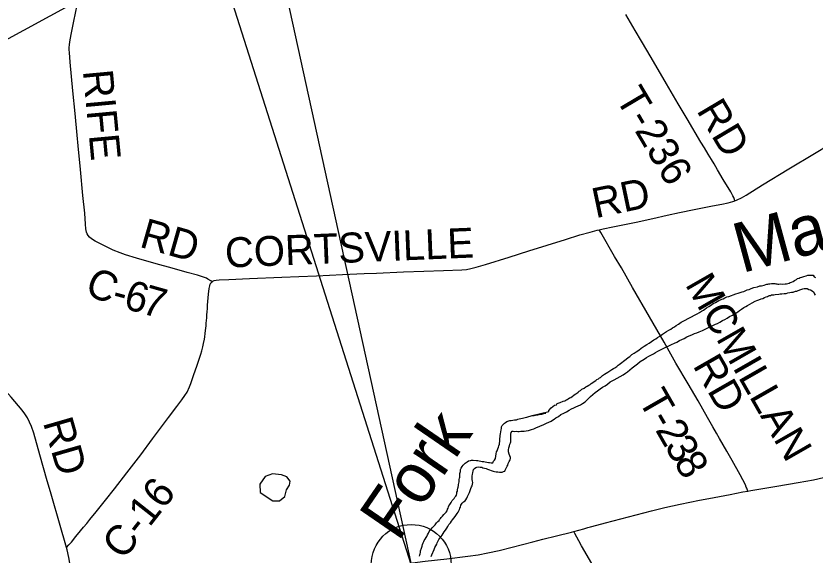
# Model space of a CAD drawing. Extents: x -19.5 to 44.1, y 0 to 22.
# Drawn here: x -17.011 to -15.494, y 5.391 to 6.414 of the extents above; entities that cross this region are included whole.
import ezdxf

# ---------------------------------------------------------------- set-up
doc = ezdxf.new("R2010")
doc.units = 0
for name, color, linetype in [('GM_X_County_Road', 7, 'Continuous'), ('GM_X_County_Road_Text', 7, 'Continuous'), ('GM_X_Minor_Lake', 7, 'Continuous'), ('GM_X_Minor_River', 7, 'Continuous'), ('GM_X_Minor_River_Text', 7, 'Continuous'), ('GM_X_Township', 7, 'Continuous'), ('GM_X_Township_Road', 7, 'Continuous'), ('GM_X_Township_Road_Text', 7, 'Continuous'), ('GM_X_US_Route', 7, 'Continuous'), ('SH_Text', 7, 'Continuous')]:
    doc.layers.add(name, color=color, linetype=linetype)

msp = doc.modelspace()

# ---------------------------------------------------------------- linework, layer by layer
at = {"layer": 'GM_X_County_Road'}
for points in [[(-16.6388, 5.9099), (-16.6413, 5.9114), (-16.6469, 5.9148), (-16.6497, 5.9164), (-16.6533, 5.918), (-16.6668, 5.9221), (-16.6859, 5.9276), (-16.7147, 5.9355), (-16.7452, 5.9441), (-16.7822, 5.9547), (-16.803, 5.9608), (-16.8135, 5.9645), (-16.8267, 5.97), (-16.8407, 5.9766), (-16.8606, 5.9868), (-16.868, 5.9911), (-16.8716, 5.9942), (-16.8741, 5.9975), (-16.8758, 6.0006), (-16.877, 6.004), (-16.8782, 6.01), (-16.8789, 6.0192), (-16.8806, 6.0397), (-16.884, 6.0737), (-16.8887, 6.1231), (-16.893, 6.1677), (-16.895, 6.188), (-16.8985, 6.2289), (-16.9031, 6.2721), (-16.9084, 6.3265), (-16.9095, 6.3451), (-16.9099, 6.3499), (-16.9099, 6.3542), (-16.9096, 6.3592), (-16.9088, 6.3653), (-16.9063, 6.3794), (-16.9011, 6.4043), (-16.8948, 6.4348)], [(-15.6467, 6.0636), (-15.642, 6.0653), (-15.6342, 6.069), (-15.6251, 6.0743), (-15.5939, 6.0935), (-15.544, 6.1239), (-15.4957, 6.1532), (-15.468, 6.1698)], [(-15.904, 6.0085), (-15.8967, 6.0102), (-15.8784, 6.014), (-15.834, 6.0232), (-15.8024, 6.03), (-15.7751, 6.0359), (-15.7515, 6.041), (-15.7235, 6.0468), (-15.6888, 6.0538), (-15.6711, 6.0573), (-15.659, 6.0597), (-15.6507, 6.0621), (-15.6467, 6.0636)], [(-16.6388, 5.9099), (-16.6375, 5.9108), (-16.6351, 5.912), (-16.6314, 5.9129), (-16.6257, 5.9135), (-16.607, 5.9144), (-16.5679, 5.9159), (-16.5064, 5.9186), (-16.4742, 5.9199), (-16.4407, 5.9213), (-16.3916, 5.9234), (-16.3501, 5.9253), (-16.3265, 5.9261), (-16.2756, 5.9285), (-16.2371, 5.9297), (-16.1993, 5.9313), (-16.1645, 5.9326), (-16.1559, 5.9333), (-16.1474, 5.9348), (-16.1379, 5.9372), (-16.12, 5.9425), (-16.075, 5.9567), (-16.0376, 5.9682), (-15.9683, 5.9902), (-15.9411, 5.9987), (-15.9214, 6.0042), (-15.9081, 6.0075), (-15.904, 6.0085)], [(-16.9154, 5.4056), (-16.9176, 5.4142), (-16.926, 5.4428), (-16.9456, 5.5108), (-16.9516, 5.5317), (-16.9658, 5.5813), (-16.9773, 5.6226), (-16.9815, 5.6349), (-16.9851, 5.6434), (-16.9894, 5.6516), (-16.9943, 5.6594), (-16.9991, 5.6659), (-17.0061, 5.6745), (-17.0204, 5.6908), (-17.0513, 5.7249), (-17.0867, 5.764), (-17.1123, 5.792), (-17.1327, 5.8146), (-17.1747, 5.862), (-17.2117, 5.9039), (-17.2222, 5.9152), (-17.2291, 5.9215), (-17.234, 5.9253)], [(-16.9154, 5.4056), (-16.9109, 5.4102), (-16.9083, 5.4129), (-16.9058, 5.4158), (-16.8973, 5.4262), (-16.8883, 5.4372), (-16.8828, 5.4439), (-16.8769, 5.4511), (-16.8711, 5.4583), (-16.859, 5.4731), (-16.8489, 5.4857), (-16.8412, 5.4954), (-16.8243, 5.5168), (-16.8005, 5.5471), (-16.7741, 5.5816), (-16.7519, 5.6116), (-16.7422, 5.6245), (-16.7214, 5.6524), (-16.7058, 5.6732), (-16.6964, 5.6856), (-16.6904, 5.6942), (-16.6864, 5.7004), (-16.6816, 5.7104), (-16.6791, 5.7167), (-16.6771, 5.7225), (-16.6739, 5.7319), (-16.6674, 5.7514), (-16.6602, 5.7725), (-16.6583, 5.779), (-16.6564, 5.7862), (-16.655, 5.7928), (-16.6534, 5.8007), (-16.6527, 5.8055), (-16.6518, 5.8116), (-16.6512, 5.8171), (-16.6503, 5.8263), (-16.6498, 5.8313), (-16.6491, 5.8411), (-16.6486, 5.8473), (-16.6483, 5.8528), (-16.6478, 5.859), (-16.6475, 5.8652), (-16.6456, 5.8862), (-16.6444, 5.8967), (-16.6433, 5.9023), (-16.6423, 5.9054), (-16.641, 5.9077), (-16.6396, 5.9092), (-16.6388, 5.9099)], [(-16.8811, 5.1933), (-16.8824, 5.1992), (-16.8847, 5.2096), (-16.8873, 5.2262), (-16.8926, 5.2612), (-16.8985, 5.3055), (-16.9024, 5.332), (-16.9066, 5.3602), (-16.911, 5.3865), (-16.9142, 5.401), (-16.9154, 5.4056)]]:
    msp.add_lwpolyline(points, dxfattribs=at)
at = {"layer": 'GM_X_Minor_Lake'}
for points in [[(-16.5244, 5.545), (-16.5382, 5.5404), (-16.5479, 5.5257), (-16.5478, 5.5098), (-16.5238, 5.4937), (-16.5109, 5.4939), (-16.5009, 5.502), (-16.4976, 5.5149), (-16.4918, 5.5235), (-16.4909, 5.5311), (-16.4968, 5.5395)], [(-16.4968, 5.5395), (-16.5069, 5.5432), (-16.5244, 5.545)]]:
    msp.add_lwpolyline(points, dxfattribs=at)
at = {"layer": 'GM_X_Minor_River'}
for points in [[(-15.6367, 5.8894), (-15.6329, 5.8905), (-15.6294, 5.8916), (-15.6268, 5.8927), (-15.6233, 5.8942), (-15.6195, 5.8953), (-15.6157, 5.8967), (-15.6104, 5.8986), (-15.6035, 5.9004), (-15.5993, 5.9018), (-15.5963, 5.9022), (-15.5932, 5.9029), (-15.5909, 5.9036), (-15.5879, 5.9043), (-15.5856, 5.905), (-15.5837, 5.9054), (-15.5818, 5.9058), (-15.5799, 5.9061), (-15.5772, 5.9064), (-15.5731, 5.9064), (-15.5708, 5.9064), (-15.5689, 5.9059), (-15.567, 5.9059), (-15.5651, 5.9055), (-15.5628, 5.9055), (-15.559, 5.9058), (-15.5552, 5.9054), (-15.551, 5.9061), (-15.5484, 5.906), (-15.5457, 5.9068), (-15.5434, 5.9071), (-15.5415, 5.9082), (-15.5388, 5.9093), (-15.5362, 5.9104), (-15.5331, 5.9123), (-15.5297, 5.9141), (-15.5278, 5.916), (-15.5243, 5.9167), (-15.5224, 5.9178), (-15.5197, 5.9185), (-15.5159, 5.92), (-15.5114, 5.9211), (-15.5083, 5.9226), (-15.5045, 5.9225), (-15.5007, 5.9224), (-15.4981, 5.9224), (-15.4958, 5.919), (-15.4936, 5.9178)], [(-16.031, 5.6557), (-15.9998, 5.6633), (-15.9994, 5.6655), (-15.9951, 5.6708), (-15.989, 5.6756), (-15.9852, 5.6763), (-15.9836, 5.6786), (-15.9783, 5.6808), (-15.9726, 5.683), (-15.9695, 5.6837), (-15.9672, 5.6848), (-15.9649, 5.6863), (-15.9627, 5.6874), (-15.9607, 5.6893), (-15.9577, 5.6904), (-15.9554, 5.6919), (-15.9519, 5.6945), (-15.9496, 5.6964), (-15.9473, 5.6978), (-15.9439, 5.7005), (-15.942, 5.7019), (-15.9397, 5.7034), (-15.937, 5.7057), (-15.9328, 5.7079), (-15.9297, 5.7101), (-15.927, 5.7116), (-15.924, 5.7135), (-15.9213, 5.7149), (-15.919, 5.7164), (-15.9163, 5.7187), (-15.9133, 5.7205), (-15.9106, 5.7224), (-15.9083, 5.7243), (-15.9056, 5.7257), (-15.9037, 5.7272), (-15.9018, 5.7283), (-15.8976, 5.7321), (-15.8941, 5.7343), (-15.8911, 5.7362), (-15.8876, 5.7384), (-15.8838, 5.741), (-15.88, 5.7432), (-15.8769, 5.7451), (-15.8742, 5.7466), (-15.8708, 5.7488), (-15.8681, 5.7514), (-15.8662, 5.7525), (-15.8639, 5.7544), (-15.8554, 5.7611), (-15.8527, 5.763), (-15.8493, 5.766), (-15.8459, 5.7682), (-15.8424, 5.7719), (-15.8374, 5.7742), (-15.8336, 5.7771), (-15.829, 5.7801), (-15.8244, 5.7838), (-15.819, 5.7876), (-15.8137, 5.7905), (-15.8095, 5.7935), (-15.8049, 5.7965), (-15.8003, 5.7995), (-15.7968, 5.8017), (-15.7934, 5.8043), (-15.7892, 5.8065), (-15.7865, 5.8084), (-15.7838, 5.8102), (-15.78, 5.8128), (-15.7762, 5.8155), (-15.772, 5.8177), (-15.7681, 5.8199), (-15.7647, 5.8225), (-15.7612, 5.8244), (-15.7582, 5.8266), (-15.7536, 5.8296), (-15.7486, 5.8333), (-15.7406, 5.837), (-15.7349, 5.8399), (-15.7287, 5.8433), (-15.723, 5.8462), (-15.718, 5.8488), (-15.7135, 5.8514), (-15.7096, 5.854), (-15.7062, 5.8559), (-15.7035, 5.8577), (-15.7001, 5.8603), (-15.6962, 5.8626), (-15.6912, 5.8659), (-15.6878, 5.8685), (-15.6836, 5.8707), (-15.6802, 5.8726), (-15.6771, 5.8741), (-15.674, 5.8755), (-15.6714, 5.8766), (-15.6687, 5.8777), (-15.6653, 5.8792), (-15.6618, 5.8811), (-15.658, 5.8821), (-15.6447, 5.8869), (-15.6405, 5.8884), (-15.6367, 5.8894)], [(-15.9813, 5.6543), (-15.9767, 5.6576), (-15.9713, 5.6606), (-15.9664, 5.6632), (-15.961, 5.6661), (-15.9564, 5.6683), (-15.9522, 5.6702), (-15.9484, 5.6724), (-15.9438, 5.6746), (-15.9396, 5.6765), (-15.9358, 5.6787), (-15.9308, 5.682), (-15.9278, 5.685), (-15.9243, 5.6884), (-15.9205, 5.6918), (-15.9162, 5.6959), (-15.9116, 5.6996), (-15.907, 5.703), (-15.9021, 5.7063), (-15.8975, 5.7097), (-15.8929, 5.7123), (-15.8883, 5.7156), (-15.8833, 5.7201), (-15.8756, 5.7234), (-15.8699, 5.7267), (-15.8642, 5.7301), (-15.8588, 5.7334), (-15.8542, 5.736), (-15.8504, 5.739), (-15.8458, 5.7427), (-15.8412, 5.7465), (-15.8366, 5.7502), (-15.8316, 5.7543), (-15.8262, 5.7584), (-15.819, 5.7629), (-15.8144, 5.7658), (-15.8098, 5.7684), (-15.8048, 5.771), (-15.801, 5.7729), (-15.7975, 5.7755), (-15.793, 5.7781), (-15.788, 5.7807), (-15.7826, 5.7832), (-15.767, 5.791), (-15.7609, 5.7932), (-15.7567, 5.7954), (-15.7517, 5.798), (-15.7471, 5.8002), (-15.7425, 5.8024), (-15.7379, 5.805), (-15.733, 5.8069), (-15.7284, 5.8091), (-15.7234, 5.8117), (-15.7185, 5.8131), (-15.7143, 5.8149), (-15.7078, 5.8175), (-15.7028, 5.8201), (-15.6979, 5.8223), (-15.6933, 5.8241), (-15.6883, 5.8267), (-15.6834, 5.8293), (-15.6792, 5.8308), (-15.675, 5.8334), (-15.67, 5.836), (-15.6654, 5.8382), (-15.6612, 5.8408), (-15.657, 5.8438), (-15.6512, 5.8463), (-15.6478, 5.8482), (-15.6444, 5.8504), (-15.6409, 5.853), (-15.6375, 5.8553), (-15.634, 5.8579), (-15.6298, 5.8608), (-15.626, 5.8631), (-15.6225, 5.8649), (-15.6183, 5.8675), (-15.6137, 5.8701), (-15.608, 5.8727), (-15.6046, 5.8742), (-15.6008, 5.8756), (-15.5966, 5.8775), (-15.5935, 5.8782), (-15.5905, 5.8797), (-15.5874, 5.8811), (-15.5847, 5.8819), (-15.5828, 5.883), (-15.5805, 5.8837), (-15.5786, 5.884), (-15.5767, 5.8848), (-15.5745, 5.8847), (-15.5726, 5.8851), (-15.5699, 5.8858), (-15.5634, 5.8865), (-15.5604, 5.8868), (-15.5573, 5.8872), (-15.5532, 5.8875), (-15.5494, 5.8878), (-15.5463, 5.8889), (-15.5421, 5.8892), (-15.5391, 5.8899)], [(-15.5391, 5.8899), (-15.536, 5.8903), (-15.5315, 5.8917), (-15.5292, 5.8921), (-15.5265, 5.8932), (-15.5212, 5.895), (-15.5174, 5.8961), (-15.5147, 5.8968), (-15.512, 5.8971), (-15.5094, 5.8967), (-15.506, 5.8952), (-15.503, 5.8944), (-15.4999, 5.8928), (-15.4969, 5.8901), (-15.4962, 5.8878), (-15.4944, 5.8844)], [(-16.031, 5.6557), (-16.0276, 5.6561), (-16.0249, 5.6568), (-16.0226, 5.6575), (-16.0207, 5.6575), (-16.0147, 5.6582), (-16.0128, 5.6585), (-16.0108, 5.6589), (-16.0089, 5.6596), (-16.0063, 5.6603), (-16.0055, 5.6606)], [(-16.1962, 5.4708), (-16.1947, 5.4727), (-16.1927, 5.4749), (-16.1919, 5.4783), (-16.1908, 5.4802), (-16.19, 5.4825), (-16.1892, 5.4844), (-16.1873, 5.487), (-16.1853, 5.4908), (-16.183, 5.4945), (-16.1811, 5.4968), (-16.1795, 5.4987), (-16.178, 5.5009), (-16.1764, 5.5028), (-16.1749, 5.5047), (-16.1745, 5.5081), (-16.1741, 5.5104), (-16.1733, 5.5122), (-16.1729, 5.5149), (-16.1724, 5.5179), (-16.172, 5.5202), (-16.1712, 5.5232), (-16.1712, 5.5251), (-16.1708, 5.5278), (-16.17, 5.5301), (-16.1696, 5.5323), (-16.1696, 5.5346), (-16.1692, 5.5369), (-16.1688, 5.5388), (-16.1687, 5.5411), (-16.1683, 5.543), (-16.1683, 5.5456), (-16.1679, 5.5475), (-16.1675, 5.5494), (-16.1671, 5.5532), (-16.1659, 5.5562), (-16.1643, 5.5589), (-16.162, 5.5619), (-16.1586, 5.5652), (-16.1544, 5.5682), (-16.1521, 5.5697), (-16.1486, 5.5708), (-16.1467, 5.5711), (-16.1433, 5.5715), (-16.1372, 5.5706), (-16.1342, 5.5706), (-16.1316, 5.5698), (-16.1289, 5.5694), (-16.1259, 5.5689), (-16.1232, 5.5685), (-16.1206, 5.5681), (-16.1172, 5.5677), (-16.1141, 5.5669), (-16.1122, 5.5668), (-16.1092, 5.5664), (-16.1062, 5.5664), (-16.1046, 5.5694), (-16.1031, 5.5713), (-16.1011, 5.5743), (-16.1003, 5.5788), (-16.0995, 5.5834), (-16.0987, 5.5872), (-16.0979, 5.5891), (-16.0963, 5.5925), (-16.0952, 5.5959), (-16.0944, 5.5981), (-16.0936, 5.6015), (-16.0932, 5.6034), (-16.0927, 5.6065), (-16.0927, 5.6091), (-16.0927, 5.6122), (-16.0923, 5.6156), (-16.0918, 5.6182), (-16.0914, 5.6213), (-16.0902, 5.6288), (-16.0898, 5.6315), (-16.0894, 5.6342), (-16.0882, 5.6368), (-16.0859, 5.6398), (-16.084, 5.6413), (-16.0817, 5.6424), (-16.0794, 5.6443), (-16.0759, 5.6457), (-16.074, 5.6465), (-16.071, 5.6464), (-16.0679, 5.6468), (-16.0649, 5.6475), (-16.063, 5.6475), (-16.0611, 5.6478), (-16.0584, 5.6489), (-16.0558, 5.6496), (-16.0531, 5.65), (-16.0497, 5.6511), (-16.047, 5.6518), (-16.0443, 5.6521), (-16.0417, 5.6525), (-16.0394, 5.6532), (-16.0375, 5.6539), (-16.0352, 5.6546), (-16.0333, 5.6554), (-16.031, 5.6557)], [(-16.1866, 5.4524), (-16.1842, 5.4554), (-16.1827, 5.458), (-16.18, 5.4614), (-16.1777, 5.4641), (-16.175, 5.4678), (-16.1734, 5.4701), (-16.1719, 5.4723), (-16.1703, 5.4753), (-16.1692, 5.4776), (-16.1684, 5.4803), (-16.1676, 5.4821), (-16.1668, 5.4856), (-16.1641, 5.4893), (-16.1614, 5.4919), (-16.1587, 5.4938), (-16.1572, 5.4961), (-16.1552, 5.4991), (-16.154, 5.5025), (-16.1521, 5.5062), (-16.1505, 5.51), (-16.149, 5.5134), (-16.1474, 5.5172), (-16.1462, 5.5206), (-16.1451, 5.5225), (-16.1438, 5.5289), (-16.1446, 5.5316), (-16.1449, 5.5346), (-16.1452, 5.5381), (-16.1452, 5.5415), (-16.1448, 5.5441), (-16.144, 5.5479), (-16.1432, 5.5506), (-16.1424, 5.5532), (-16.1405, 5.5551), (-16.1385, 5.557), (-16.1363, 5.5581), (-16.134, 5.5584), (-16.1298, 5.558), (-16.1271, 5.5579), (-16.1249, 5.5568), (-16.1219, 5.5563), (-16.1184, 5.5552), (-16.1162, 5.5544), (-16.1143, 5.5536), (-16.1124, 5.5528), (-16.109, 5.5516), (-16.1052, 5.5504), (-16.1026, 5.5496), (-16.0999, 5.5488), (-16.0965, 5.5488), (-16.0935, 5.5487), (-16.0904, 5.5487), (-16.0885, 5.5486), (-16.0855, 5.5497), (-16.0832, 5.5505), (-16.0824, 5.5524), (-16.0785, 5.5595), (-16.0777, 5.5618), (-16.0766, 5.5648), (-16.075, 5.5686), (-16.0731, 5.5716), (-16.0723, 5.5742), (-16.0722, 5.5761), (-16.0737, 5.5792), (-16.0748, 5.5823), (-16.0763, 5.5868), (-16.0762, 5.5906), (-16.0758, 5.5944), (-16.0746, 5.5986), (-16.0734, 5.6016), (-16.0723, 5.6039), (-16.0719, 5.6058), (-16.0718, 5.6096), (-16.0718, 5.6122), (-16.0718, 5.6141), (-16.0721, 5.6164), (-16.0717, 5.6206), (-16.0713, 5.6236), (-16.069, 5.6263), (-16.0671, 5.6262), (-16.0648, 5.6258), (-16.0618, 5.6262), (-16.0587, 5.6257), (-16.0557, 5.6257), (-16.0526, 5.626), (-16.0496, 5.6264), (-16.0466, 5.6263), (-16.0428, 5.627), (-16.0382, 5.6277), (-16.0325, 5.6295), (-16.0283, 5.6306), (-16.0241, 5.6325), (-16.0092, 5.6391), (-16.0042, 5.6413), (-15.9997, 5.6435), (-15.9955, 5.6453), (-15.9924, 5.6472), (-15.9893, 5.649), (-15.9863, 5.6517), (-15.9813, 5.6543)], [(-16.2454, 5.3887), (-16.2446, 5.3913), (-16.2439, 5.3936), (-16.2434, 5.3958), (-16.243, 5.3993), (-16.2414, 5.4042), (-16.2403, 5.408), (-16.2395, 5.411), (-16.2379, 5.414), (-16.2367, 5.4166), (-16.236, 5.4185), (-16.2344, 5.4212), (-16.2328, 5.4242), (-16.2313, 5.4264), (-16.2297, 5.4295), (-16.2282, 5.4325), (-16.2266, 5.4359), (-16.2247, 5.4381), (-16.2231, 5.4404), (-16.2212, 5.443), (-16.2151, 5.4483), (-16.2131, 5.4524), (-16.2101, 5.4546), (-16.2081, 5.4569), (-16.207, 5.4588), (-16.2054, 5.4607), (-16.2039, 5.4625), (-16.2016, 5.4652), (-16.1989, 5.4678), (-16.1962, 5.4708)], [(-16.2227, 5.3883), (-16.2215, 5.3917), (-16.2176, 5.4019), (-16.216, 5.4057), (-16.2141, 5.4087), (-16.2125, 5.4117), (-16.2113, 5.414), (-16.2102, 5.417), (-16.2082, 5.4204), (-16.2063, 5.4234), (-16.2043, 5.4261), (-16.2024, 5.4291), (-16.2001, 5.4321), (-16.1982, 5.4351), (-16.1958, 5.4381), (-16.1931, 5.4422), (-16.1912, 5.4456), (-16.1893, 5.449), (-16.1866, 5.4524)]]:
    msp.add_lwpolyline(points, dxfattribs=at)
at = {"layer": 'GM_X_Township'}
msp.add_lwpolyline([(-12.8914, 6.3794), (-13.1137, 6.4041), (-13.3583, 6.4294), (-13.4411, 6.4345), (-13.5998, 6.4444), (-14.0891, 6.4899), (-14.1777, 7.0231), (-14.285, 7.035), (-14.659, 7.083), (-15.5678, 7.2141), (-15.56, 7.1963), (-16.1193, 6.8606), (-16.1939, 6.8159), (-16.2133, 6.8121), (-16.897, 6.4411), (-17.1473, 6.3052)], dxfattribs=at)
at = {"layer": 'GM_X_Township_Road'}
for points in [[(-15.6467, 6.0636), (-15.6475, 6.0658), (-15.6487, 6.0695), (-15.6503, 6.0728), (-15.6545, 6.0806), (-15.6685, 6.104), (-15.6796, 6.122), (-15.686, 6.1334), (-15.691, 6.1419), (-15.6971, 6.1518), (-15.7044, 6.164), (-15.7112, 6.1749), (-15.7371, 6.2188), (-15.7541, 6.2477), (-15.7761, 6.2852), (-15.8056, 6.3356), (-15.8239, 6.3666), (-15.8359, 6.387), (-15.8537, 6.4168)], [(-15.6221, 5.5126), (-15.624, 5.5179), (-15.6248, 5.5202), (-15.6265, 5.5242), (-15.6367, 5.5434), (-15.6517, 5.5706), (-15.6617, 5.5884), (-15.6756, 5.6126), (-15.6813, 5.6223), (-15.6882, 5.6347), (-15.6985, 5.6524), (-15.7164, 5.6837), (-15.7352, 5.7159), (-15.7583, 5.7556), (-15.7809, 5.7949), (-15.8088, 5.8433), (-15.8406, 5.8988), (-15.8619, 5.936), (-15.8748, 5.9579), (-15.9009, 6.003), (-15.904, 6.0085)], [(-15.7034, 5.0119), (-15.7159, 5.033), (-15.7253, 5.049), (-15.7408, 5.0753), (-15.7528, 5.0956), (-15.7647, 5.116), (-15.7726, 5.1293), (-15.784, 5.1485), (-15.8027, 5.1794), (-15.8226, 5.2124), (-15.8314, 5.2274), (-15.8518, 5.2622), (-15.86, 5.2761), (-15.8782, 5.3072), (-15.9045, 5.3523), (-15.9375, 5.4086), (-15.9427, 5.4178), (-15.9502, 5.4321), (-15.9521, 5.4357)]]:
    msp.add_lwpolyline(points, dxfattribs=at)
at = {"layer": 'GM_X_US_Route'}
for points in [[(-16.0694, 5.4062), (-16.0298, 5.4164), (-16.0111, 5.4211), (-15.9851, 5.4273), (-15.9568, 5.4344), (-15.9521, 5.4357), (-15.943, 5.4381), (-15.9335, 5.441), (-15.9258, 5.4434), (-15.9205, 5.4449), (-15.8989, 5.4506), (-15.8923, 5.4524), (-15.8046, 5.4752), (-15.7795, 5.4815), (-15.7504, 5.4878), (-15.7138, 5.4951), (-15.6962, 5.4985), (-15.6552, 5.5059), (-15.6315, 5.5109), (-15.6221, 5.5126), (-15.6162, 5.5136), (-15.5672, 5.5221), (-15.5262, 5.5288), (-15.4974, 5.534), (-15.478, 5.5383)], [(-16.3548, 5.3589), (-16.3142, 5.3677), (-16.2965, 5.3711), (-16.2775, 5.374), (-16.2343, 5.3793), (-16.193, 5.3838), (-16.1535, 5.3887), (-16.1338, 5.3917), (-16.1154, 5.3951), (-16.0942, 5.3998), (-16.0694, 5.4062)]]:
    msp.add_lwpolyline(points, dxfattribs=at)
at = {"layer": 'SH_Text'}
msp.add_lwpolyline([(-16.9061, 8.3173), (-16.2609, 5.3732), (-17.1978, 8.3177)], close=True, dxfattribs=at)
msp.add_circle((-16.2609, 5.3732), 0.0759, dxfattribs=at)

# ---------------------------------------------------------------- texts
at = {"layer": 'GM_X_County_Road_Text'}
for s, height, rotation, p in [('RIFE', 0.05682, 275.3358, (-16.8842, 6.3102)), ('RD', 0.05682, 11.8887, (-15.911, 6.0302)), ('RD', 0.05682, 344.1895, (-16.7787, 5.9765)), ('CORTSVILLE', 0.05682, 2.3487, (-16.6133, 5.9365)), ('C', 0.0568, 335.8584, (-16.8832, 5.8884)), ('6', 0.0568, 344.2369, (-16.8092, 5.86)), ('7', 0.0568, 344.3033, (-16.7754, 5.8504)), ('-', 0.0568, 344.7777, (-16.8316, 5.8661)), ('RD', 0.05682, 286.1458, (-16.9602, 5.643)), ('C-16', 0.05682, 51.7755, (-16.8074, 5.3797))]:
    msp.add_text(s, height=height, rotation=rotation, dxfattribs=at).set_placement(p)
at = {"layer": 'GM_X_Minor_River_Text'}
for s, height, rotation, p in [('Massies', 0.09469, 15.2703, (-15.6336, 5.9258)), ('Fork', 0.09468, 55.5067, (-16.2859, 5.4142))]:
    msp.add_text(s, height=height, rotation=rotation, dxfattribs=at).set_placement(p)
at = {"layer": 'GM_X_Township_Road_Text'}
for s, height, rotation, p in [('T-236', 0.05682, 300.6792, (-15.8743, 6.2587)), ('RD', 0.05682, 300.7072, (-15.7203, 6.2349)), ('MCMILLAN', 0.05682, 299.7763, (-15.7419, 5.9049)), ('RD', 0.05682, 299.8675, (-15.7274, 5.7509)), ('T', 0.0568, 299.848, (-15.8312, 5.6858)), ('-', 0.0568, 299.8446, (-15.8101, 5.649)), ('2', 0.0568, 299.8638, (-15.7985, 5.6287)), ('3', 0.0568, 299.9083, (-15.781, 5.5983)), ('8', 0.0568, 300.1036, (-15.7635, 5.5678))]:
    msp.add_text(s, height=height, rotation=rotation, dxfattribs=at).set_placement(p)

doc.saveas('drawing.dxf')
